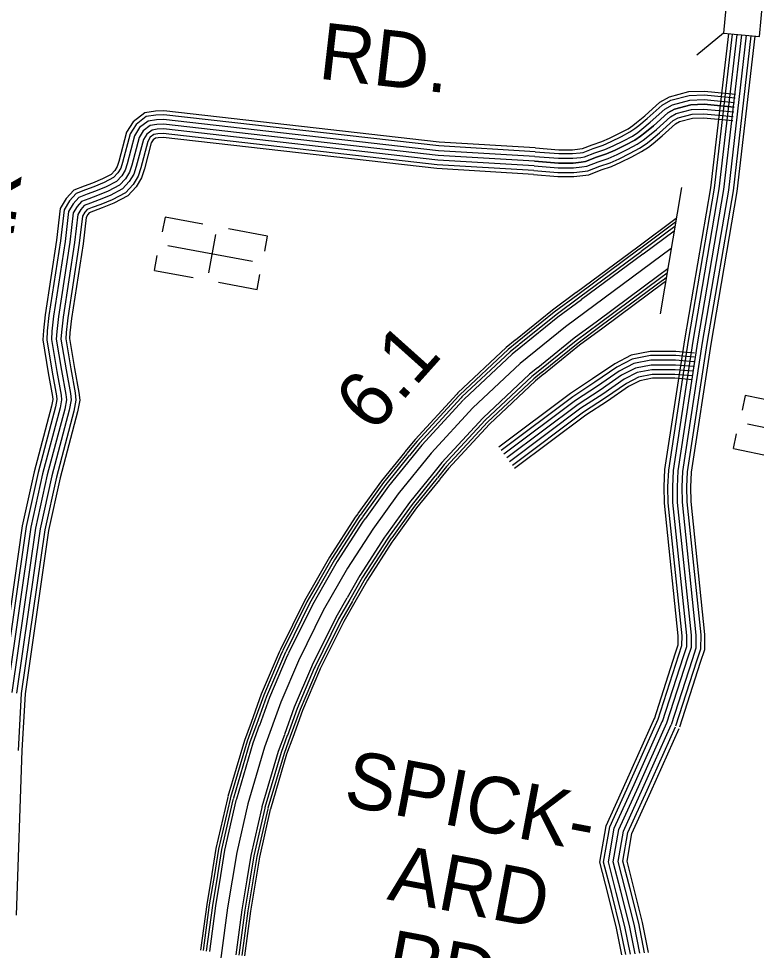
# Model space of a CAD drawing. Extents: x 1788175 to 1969470, y 584502 to 738744.
# Drawn here: x 1840962 to 1845792, y 638570 to 644675 of the extents above; entities that cross this region are included whole.
import ezdxf

# ---------------------------------------------------------------- set-up
doc = ezdxf.new("R2010")
doc.units = 0
for name, color, linetype in [('DESIGN - ROW - Right-of-Way and Easement Labels', 7, 'Continuous'), ('DESIGN - TRAFFIC CONTROL PERMANENT - Signalization', 7, 'Continuous'), ('DESIGN - UTILITIES - Cable (Underground) with Text', 7, 'Continuous'), ('SURVEY - CENTERLINE - Preliminary Text', 7, 'Continuous'), ('SURVEY - CONTOURS - Index with Text', 7, 'Continuous'), ('SURVEY - DRAINAGE - Storm Sewer', 7, 'Continuous'), ('SURVEY - TRANSPORTATION - Roads', 7, 'Continuous')]:
    doc.layers.add(name, color=color, linetype=linetype)

msp = doc.modelspace()

# ---------------------------------------------------------------- linework, layer by layer
at = {"layer": 'DESIGN - UTILITIES - Cable (Underground) with Text'}
for p, q in [((1841920, 643374.4), (1841902.2, 643277.8)), ((1842167.3, 643328.8), (1841920.1, 643374.5)), ((1842206.8, 643010.1), (1842252.8, 643259.5)), ((1842591.9, 643250.4), (1842335.4, 643297.8)), ((1842573.8, 643152.4), (1842591.8, 643249.8)), ((1841851.5, 643025.1), (1841869.6, 643122.9)), ((1841851.4, 643024.9), (1842105.3, 642978)), ((1842523.3, 642900.7), (1842541.4, 642998.8)), ((1842270.8, 642947.4), (1842523.3, 642900.8)), ((1845718.1, 642205.9), (1845698.2, 642109.8)), ((1845964.4, 642154.9), (1845718.2, 642206.1)), ((1845641.9, 641858.2), (1845662.1, 641955.6)), ((1845641.8, 641858), (1845894.5, 641805.5))]:
    msp.add_line(p, q, dxfattribs=at)
for points in [[(1842492.8, 643084.7), (1841939.1, 643187)], [(1846284.3, 641903.7), (1845733.1, 642018.2)]]:
    msp.add_lwpolyline(points, dxfattribs=at)
at = {"layer": 'SURVEY - CENTERLINE - Preliminary Text'}
for points in [[(1845268, 643365.2), (1845016.2, 643178.6)], [(1845263.8, 643340.3), (1845026.6, 643164.5)], [(1845259.1, 643311.9), (1845038.5, 643148.5)], [(1845254.3, 643283.1), (1845050.6, 643132.2)], [(1845235.2, 643168.5), (1844542.4, 642655.1), (1844245.9, 642415.6), (1843936.4, 642125.1), (1843661.9, 641827.2), (1843447.3, 641561.6), (1843279.8, 641329.3), (1843115.9, 641075.5), (1842956.4, 640796.1), (1842793.7, 640466.7), (1842679.4, 640197.2), (1842572.4, 639902.6), (1842462.7, 639531), (1842389.5, 639210.6), (1842329.8, 638849.8), (1841456.3, 632272.6)], [(1845015.4, 643178), (1844613.7, 642880.4)], [(1845025.8, 643164), (1844624.1, 642866.3)], [(1845037.8, 643147.9), (1844636, 642850.2)], [(1845049.8, 643131.6), (1844648.1, 642833.9)], [(1845213, 643035.5), (1845154.4, 642992)], [(1845208.2, 643006.6), (1845167.2, 642976.3)], [(1845153.7, 642991.5), (1844752, 642693.8)], [(1845166.5, 642975.7), (1844764.8, 642678)], [(1845178.4, 642959.6), (1844776.7, 642662)], [(1845188.8, 642945.6), (1844787.1, 642647.9)], [(1845203.5, 642978.2), (1845179.1, 642960.2)], [(1845199.4, 642953.4), (1845189.5, 642946.1)], [(1844613, 642879.8), (1844457.6, 642764.7), (1844214.6, 642568.3)], [(1844623.4, 642865.8), (1844468.3, 642750.8), (1844225.6, 642554.7)], [(1844635.3, 642849.7), (1844480.5, 642735), (1844238.2, 642539.2)], [(1844647.4, 642833.4), (1844492.9, 642719), (1844250.9, 642523.4)], [(1844751.2, 642693.2), (1844599.7, 642581), (1844360.5, 642387.7)], [(1844764, 642677.5), (1844612.1, 642564.9), (1844374, 642372.5)], [(1844775.9, 642661.4), (1844624.4, 642549.1), (1844386.6, 642357)], [(1844786.4, 642647.4), (1844635.1, 642535.3), (1844397.6, 642343.4)], [(1844213.9, 642567.8), (1844154.9, 642520.1), (1843837.9, 642222.6), (1843831.3, 642215.4)], [(1844224.9, 642554.2), (1844166.4, 642506.9), (1843850.4, 642210.3), (1843844.2, 642203.6)], [(1844237.4, 642538.6), (1844179.5, 642491.8), (1843864.6, 642196.2), (1843858.9, 642190)], [(1844250.2, 642522.8), (1844192.9, 642476.5), (1843879, 642181.9), (1843873.8, 642176.3)], [(1844359.8, 642387.2), (1844307.5, 642344.9), (1844003, 642059.1), (1844002.1, 642058.1)], [(1844373.3, 642371.9), (1844320.9, 642329.6), (1844017.4, 642044.8), (1844017.6, 642045)], [(1844385.8, 642356.4), (1844334, 642314.5), (1844031.7, 642030.7), (1844032.3, 642031.5)], [(1844396.8, 642342.8), (1844345.5, 642301.3), (1844044.1, 642018.4), (1844045.2, 642019.6)], [(1843830.7, 642214.8), (1843557, 641917.8), (1843490.9, 641836)], [(1843843.6, 642202.9), (1843570.2, 641906.4), (1843504.5, 641825)], [(1843858.3, 642189.4), (1843585.4, 641893.3), (1843520.1, 641812.4)], [(1843873.2, 642175.6), (1843600.8, 641880), (1843535.8, 641799.7)], [(1844001.4, 642057.4), (1843732.9, 641766), (1843671.5, 641690.1)], [(1844017, 642044.3), (1843748.2, 641752.7), (1843687.9, 641678)], [(1844031.7, 642030.8), (1843763.4, 641739.7), (1843703.4, 641665.5)], [(1844044.6, 642018.9), (1843776.6, 641728.2), (1843717, 641654.5)], [(1843490.3, 641835.3), (1843337.2, 641645.8), (1843182.8, 641431.7)], [(1843503.9, 641824.3), (1843351.1, 641635.1), (1843197, 641421.5)], [(1843519.5, 641811.7), (1843367, 641623), (1843213.3, 641409.8)], [(1843535.3, 641799), (1843383.1, 641610.7), (1843229.7, 641397.9)], [(1843671, 641689.4), (1843521.8, 641504.8), (1843371.2, 641295.9)], [(1843687.3, 641677.3), (1843538, 641492.5), (1843388.2, 641284.7)], [(1843702.9, 641664.8), (1843553.9, 641480.3), (1843404.4, 641273)], [(1843716.5, 641653.8), (1843567.8, 641469.7), (1843418.6, 641262.8)], [(1843182.3, 641431), (1843165.4, 641407.5), (1842997.5, 641147.5), (1842910.1, 640994.4)], [(1843196.5, 641420.7), (1843179.8, 641397.6), (1843012.5, 641138.4), (1842925.3, 640985.8)], [(1843212.7, 641409), (1843196.4, 641386.3), (1843029.6, 641128), (1842942.7, 640975.8)], [(1843229.2, 641397.2), (1843213.1, 641374.9), (1843046.9, 641117.5), (1842960.3, 640965.8)], [(1843370.7, 641295.1), (1843357.2, 641276.5), (1843196, 641026.9), (1843111.7, 640879.3)], [(1843387.7, 641284), (1843374, 641265), (1843213.4, 641016.3), (1843129.8, 640870)], [(1843403.9, 641272.3), (1843390.5, 641253.8), (1843230.5, 641005.9), (1843147.2, 640860.1)], [(1843418.1, 641262.1), (1843405, 641243.9), (1843245.4, 640996.8), (1843162.4, 640851.4)], [(1842909.6, 640993.7), (1842834, 640861.2), (1842676.4, 640542.2)], [(1842924.8, 640985), (1842849.5, 640853), (1842692.1, 640534.4)], [(1842942.2, 640975.1), (1842867.1, 640843.6), (1842710.1, 640525.6)], [(1842959.8, 640965), (1842885, 640834), (1842728.2, 640516.6)], [(1843111.3, 640878.5), (1843039.1, 640752.1), (1842884.6, 640439.4)], [(1843129.4, 640869.2), (1843057, 640742.6), (1842903.2, 640431.2)], [(1843146.7, 640859.3), (1843074.7, 640733.2), (1842921.2, 640422.3)], [(1843161.9, 640850.6), (1843090.1, 640725), (1842936.9, 640414.6)], [(1842676, 640541.4), (1842667.7, 640524.5), (1842550.4, 640247.9), (1842483.5, 640063.6)], [(1842691.7, 640533.6), (1842683.6, 640517.2), (1842566.7, 640241.5), (1842499.9, 640057.6)], [(1842709.7, 640524.8), (1842701.8, 640508.8), (1842585.3, 640234.2), (1842518.7, 640050.8)], [(1842727.8, 640515.8), (1842720.2, 640500.4), (1842604.2, 640226.7), (1842537.8, 640043.9)], [(1842884.2, 640438.5), (1842878.9, 640427.6), (1842766.6, 640162.9), (1842701.8, 639984.4)], [(1842902.8, 640430.4), (1842897.3, 640419.2), (1842785.5, 640155.5), (1842721.1, 639978.3)], [(1842920.8, 640421.5), (1842915.5, 640410.9), (1842804.1, 640148.1), (1842739.9, 639971.5)], [(1842936.5, 640413.8), (1842931.4, 640403.6), (1842820.4, 640141.7), (1842756.4, 639965.5)], [(1842483.2, 640062.8), (1842440.8, 639945.9), (1842332, 639577.5)], [(1842499.6, 640056.8), (1842457.4, 639940.5), (1842348.8, 639572.5)], [(1842518.4, 640050), (1842476.4, 639934.2), (1842367.9, 639566.9)], [(1842537.5, 640043.1), (1842495.7, 639927.9), (1842387.4, 639561.1)], [(1842701.5, 639983.5), (1842661.5, 639873.4), (1842554.7, 639511.7)], [(1842720.8, 639977.5), (1842680.7, 639867), (1842574.4, 639506.9)], [(1842739.6, 639970.6), (1842699.7, 639860.8), (1842593.6, 639501.2)], [(1842756.1, 639964.7), (1842716.4, 639855.3), (1842610.4, 639496.2)], [(1842331.7, 639576.6), (1842328.6, 639566.1), (1842253.5, 639237.3), (1842226, 639070.7)], [(1842348.5, 639571.7), (1842345.6, 639561.7), (1842270.7, 639233.9), (1842243.2, 639067.9)], [(1842367.7, 639566), (1842364.9, 639556.6), (1842290.3, 639230.1), (1842263, 639064.6)], [(1842387.1, 639560.2), (1842384.6, 639551.5), (1842310.2, 639226.2), (1842283, 639061.3)], [(1842554.4, 639510.8), (1842553.4, 639507.3), (1842481.5, 639192.5), (1842455.1, 639032.8)], [(1842574.1, 639506), (1842573, 639502.2), (1842501.4, 639188.6), (1842475.2, 639030.4)], [(1842593.3, 639500.3), (1842592.4, 639497.1), (1842521, 639184.7), (1842495, 639027.1)], [(1842610.1, 639495.4), (1842609.3, 639492.7), (1842538.2, 639181.3), (1842512.2, 639024.3)], [(1842225.8, 639069.8), (1842192.8, 638870.2), (1842153, 638570.8)], [(1842243.1, 639067), (1842210.1, 638867.6), (1842170.4, 638568.4)], [(1842262.8, 639063.7), (1842229.9, 638864.7), (1842190.2, 638565.8)], [(1842282.8, 639060.4), (1842249.9, 638861.7), (1842210.3, 638563.1)], [(1842454.9, 639031.9), (1842422.5, 638835.9), (1842383.2, 638540.2)], [(1842475.1, 639029.5), (1842442.6, 638832.9), (1842403.4, 638538.4)], [(1842494.8, 639026.2), (1842462.3, 638830), (1842423.3, 638535.8)], [(1842512.1, 639023.4), (1842479.7, 638827.4), (1842440.6, 638533.5)]]:
    msp.add_lwpolyline(points, dxfattribs=at)
at = {"layer": 'SURVEY - CONTOURS - Index with Text'}
for points in [[(1845124.4, 640087.2), (1845261.4, 640513.5), (1845280.4, 640571.4), (1845281.1, 640631), (1845190.3, 641500.3), (1845188.9, 641608.7), (1845193.9, 641719.9), (1845323.7, 642570.7), (1845494.4, 643567.1), (1845611, 644576.4)], [(1845147.9, 640079.6), (1845284.9, 640505.9), (1845305, 640567.3), (1845305.9, 640632.1), (1845215, 641501.8), (1845213.6, 641608.3), (1845218.5, 641717.4), (1845348.1, 642566.7), (1845518.9, 643563.6), (1845635.6, 644574.1)], [(1845177.4, 640070.1), (1845314.4, 640496.3), (1845336, 640562.1), (1845336.9, 640633.6), (1845246, 641503.6), (1845244.6, 641607.8), (1845249.4, 641714.4), (1845378.7, 642561.8), (1845549.6, 643559.2), (1845666.5, 644571.2)], [(1845206.9, 640060.6), (1845343.8, 640486.7), (1845366.9, 640557), (1845367.9, 640635), (1845276.9, 641505.4), (1845275.6, 641607.3), (1845280.3, 641711.4), (1845409.3, 642556.8), (1845580.3, 643554.8), (1845697.3, 644568.4)], [(1845206.9, 640060.6), (1845343.8, 640486.7), (1845366.9, 640557), (1845367.9, 640635), (1845276.9, 641505.4), (1845275.6, 641607.3), (1845280.3, 641711.4), (1845409.3, 642556.8), (1845580.3, 643554.8), (1845697.3, 644568.3)], [(1845236.4, 640051.1), (1845373.3, 640477.1), (1845397.8, 640551.8), (1845398.9, 640636.4), (1845307.9, 641507.2), (1845306.6, 641606.8), (1845311.2, 641708.3), (1845439.9, 642551.9), (1845611, 643550.4), (1845728.2, 644565.5)], [(1845265.9, 640041.7), (1845402.8, 640467.6), (1845428.8, 640546.7), (1845430, 640637.8), (1845338.9, 641509), (1845337.7, 641606.3), (1845342.1, 641705.3), (1845470.5, 642546.9), (1845641.7, 643546), (1845759.1, 644562.6)], [(1845290.4, 640033.8), (1845427.3, 640459.6), (1845454.4, 640542.4), (1845455.7, 640639), (1845364.6, 641510.5), (1845363.4, 641605.9), (1845367.7, 641702.8), (1845495.9, 642542.8), (1845667.2, 643542.4), (1845784.7, 644560.2)], [(1845646.8, 644094.8), (1845449.7, 644113.6), (1845362.1, 644110.5), (1845255.7, 644082.3), (1845211.9, 644057.3), (1845118, 643972.8), (1845061.7, 643925.9), (1845033.6, 643904), (1844996, 643879), (1844936.6, 643847.7), (1844867.8, 643813.3), (1844811.4, 643788.2), (1844745.7, 643766.3), (1844673.8, 643738.2), (1844645.6, 643735), (1844592.5, 643728.8), (1844495.5, 643728.8), (1844339, 643741)], [(1844344.3, 643828.5), (1843715.8, 643866.1), (1841912.7, 644071.5), (1841857.2, 644068.2), (1841787.3, 644057.7), (1841711, 643999.6), (1841668.2, 643930.3), (1841617.9, 643739.8), (1841606.5, 643705.4), (1841590.7, 643679.1), (1841567.6, 643654.2), (1841511.3, 643624.2), (1841445.1, 643597.4), (1841389.9, 643576.8), (1841322.5, 643550.5), (1841273.3, 643496.5), (1841233.6, 643430.3), (1841210.1, 643222.9), (1841134.4, 642733.9), (1841123.3, 642632), (1841119.1, 642569.9), (1841155.5, 642353.8), (1841183.1, 642200.1), (1841185.6, 642180.1), (1841177.5, 642136.5), (1841063.5, 641706.5), (1840985, 641352.6), (1840830, 640267.8)], [(1844342.7, 643802.9), (1843713.6, 643840.5), (1841912, 644045.7), (1841859.9, 644042.6), (1841797.6, 644033.3), (1841730.3, 643982.1), (1841692.1, 643920.1), (1841642.6, 643732.4), (1841630, 643694.6), (1841611.4, 643663.6), (1841583.5, 643633.5), (1841522.2, 643600.9), (1841454.4, 643573.5), (1841399.1, 643552.8), (1841337.5, 643528.7), (1841294, 643481.1), (1841258.5, 643421.9), (1841235.6, 643219.5), (1841159.9, 642730.5), (1841148.9, 642629.7), (1841145, 642571.2), (1841180.8, 642358.2), (1841208.5, 642204), (1841211.6, 642179.3), (1841202.6, 642130.9), (1841088.5, 641700.5), (1841010.3, 641348), (1840855.6, 640265.3)], [(1844340.9, 643771.9), (1843710.9, 643809.6), (1841911.1, 644014.6), (1841863.2, 644011.8), (1841810.1, 644003.8), (1841753.7, 643960.9), (1841720.9, 643907.7), (1841672.3, 643723.6), (1841658.3, 643681.6), (1841636.3, 643644.9), (1841602.6, 643608.6), (1841535.3, 643572.8), (1841465.7, 643544.6), (1841410.2, 643523.9), (1841355.5, 643502.5), (1841319, 643462.4), (1841288.6, 643411.7), (1841266.3, 643215.4), (1841190.7, 642726.5), (1841179.8, 642627), (1841176.2, 642572.7), (1841211.4, 642363.5), (1841239.2, 642208.6), (1841242.9, 642178.3), (1841232.8, 642124.1), (1841118.6, 641693.1), (1841040.8, 641342.4), (1840886.5, 640262.2)], [(1844339, 643741), (1843708.2, 643778.7), (1841910.3, 643983.5), (1841866.4, 643980.9), (1841822.5, 643974.3), (1841777, 643939.7), (1841749.7, 643895.3), (1841702, 643714.7), (1841686.6, 643668.5), (1841661.2, 643626.2), (1841621.8, 643583.7), (1841548.4, 643544.7), (1841476.9, 643515.7), (1841421.3, 643494.9), (1841373.6, 643476.2), (1841344, 643443.8), (1841318.6, 643401.5), (1841297.1, 643211.3), (1841221.4, 642722.4), (1841210.7, 642624.3), (1841207.3, 642574.3), (1841241.9, 642368.8), (1841269.9, 642213.3), (1841274.3, 642177.4), (1841263.1, 642117.2), (1841148.8, 641685.8), (1841071.3, 641336.9), (1840917.3, 640259.1)], [(1844339, 643741), (1843708.2, 643778.7), (1841910.3, 643983.5), (1841866.4, 643980.9), (1841822.5, 643974.3), (1841777, 643939.7), (1841749.7, 643895.3), (1841702, 643714.7), (1841686.6, 643668.5), (1841661.2, 643626.2), (1841621.8, 643583.7), (1841548.4, 643544.7), (1841476.9, 643515.7), (1841421.3, 643494.9), (1841373.6, 643476.2), (1841344, 643443.8), (1841318.6, 643401.5), (1841297.1, 643211.3), (1841221.4, 642722.4), (1841210.7, 642624.3), (1841207.3, 642574.3), (1841241.9, 642368.8), (1841269.9, 642213.3), (1841274.3, 642177.4), (1841263.1, 642117.2), (1841148.8, 641685.8), (1841071.3, 641336.9), (1840917.3, 640259.1)], [(1844337.2, 643710), (1843705.5, 643747.8), (1841909.4, 643952.4), (1841869.6, 643950.1), (1841835, 643944.8), (1841800.4, 643918.5), (1841778.5, 643883), (1841731.8, 643705.9), (1841715, 643655.5), (1841686.1, 643607.5), (1841641, 643558.7), (1841561.6, 643516.5), (1841488.1, 643486.8), (1841432.3, 643465.9), (1841391.6, 643450), (1841369, 643425.2), (1841348.6, 643391.3), (1841327.8, 643207.2), (1841252.2, 642718.4), (1841241.6, 642621.6), (1841238.5, 642575.8), (1841272.4, 642374.2), (1841300.5, 642217.9), (1841305.7, 642176.4), (1841293.3, 642110.4), (1841178.9, 641678.5), (1841101.9, 641331.3), (1840948.2, 640256)], [(1844335.3, 643679.1), (1843702.9, 643716.9), (1841908.6, 643921.3), (1841872.9, 643919.2), (1841847.5, 643915.4), (1841823.8, 643897.3), (1841807.3, 643870.6), (1841761.5, 643697), (1841743.3, 643642.5), (1841711.1, 643588.8), (1841660.2, 643533.8), (1841574.7, 643488.4), (1841499.4, 643457.9), (1841443.4, 643437), (1841409.6, 643423.8), (1841394, 643406.6), (1841378.7, 643381.1), (1841358.5, 643203), (1841282.9, 642714.3), (1841272.5, 642618.9), (1841269.7, 642577.4), (1841303, 642379.5), (1841331.2, 642222.6), (1841337, 642175.4), (1841323.6, 642103.6), (1841209, 641671.1), (1841132.4, 641325.7), (1840979.1, 640253), (1840958.1, 639880.1)], [(1844333.9, 643654.4), (1843700.7, 643692.2), (1841907.9, 643896.5), (1841875.4, 643894.6), (1841857.4, 643891.9), (1841842.4, 643880.4), (1841830.2, 643860.7), (1841785.2, 643689.9), (1841765.9, 643632.1), (1841730.9, 643573.9), (1841675.5, 643514), (1841585.2, 643466), (1841508.4, 643434.8), (1841452.2, 643413.9), (1841424, 643402.9), (1841413.9, 643391.8), (1841402.7, 643373), (1841383, 643199.8), (1841307.4, 642711.1), (1841297.1, 642616.7), (1841294.5, 642578.6), (1841327.3, 642383.7), (1841355.6, 642226.3), (1841362, 642174.7), (1841347.7, 642098.1), (1841233, 641665.3), (1841156.7, 641321.3), (1841003.7, 640250.5), (1840982.8, 639879), (1840944.6, 638801.2)], [(1844912, 638540.1), (1844876.6, 638715.1), (1844821.2, 638936.3), (1844767, 639147.5), (1844808.1, 639387.2), (1844941.9, 639680.5), (1845127.8, 640096)], [(1844936.8, 638542.6), (1844900.7, 638720.5), (1844845.2, 638942.4), (1844792.2, 639148.6), (1844831.9, 639379.9), (1844964.4, 639670.3), (1845150.3, 640085.9)], [(1844967.8, 638545.6), (1844931, 638727.4), (1844875.2, 638950), (1844823.9, 639149.9), (1844861.8, 639370.7), (1844992.7, 639657.5), (1845178.6, 640073.3)], [(1844998.8, 638548.6), (1844961.2, 638734.2), (1844905.3, 638957.6), (1844855.6, 639151.1), (1844891.6, 639361.5), (1845020.9, 639644.8), (1845206.9, 640060.6)], [(1845029.8, 638551.6), (1844991.4, 638741.1), (1844935.3, 638965.3), (1844887.3, 639152.4), (1844921.5, 639352.3), (1845049.2, 639632), (1845235.2, 640048)], [(1845060.8, 638554.6), (1845021.7, 638747.9), (1844965.4, 638972.9), (1844918.9, 639153.7), (1844951.4, 639343.1), (1845077.4, 639619.3), (1845263.5, 640035.3)], [(1845086.6, 638557.1), (1845046.8, 638753.6), (1844990.3, 638979.2), (1844945.2, 639154.8), (1844976.2, 639335.4), (1845100.9, 639608.7), (1845287, 640024.8)]]:
    msp.add_lwpolyline(points, dxfattribs=at)
at = {"layer": 'SURVEY - DRAINAGE - Storm Sewer'}
msp.add_line((1845576.5, 644579.6), (1845401.8, 644434.6), dxfattribs=at)
msp.add_lwpolyline([(1845598.6, 644816.2), (1845576.5, 644579.6), (1845813.1, 644557.6), (1845835.1, 644794.2)], close=True, dxfattribs=at)
msp.add_lwpolyline([(1845301, 643569.2), (1845162.8, 642739.8)], dxfattribs=at)
at = {"layer": 'SURVEY - TRANSPORTATION - Roads'}
for points in [[(1844343.9, 643802.8), (1844497.9, 643790.8), (1844588.8, 643790.8), (1844638.6, 643796.6), (1844658.8, 643798.9), (1844724.6, 643824.6), (1844789, 643846.1), (1844841.3, 643869.3), (1844908.3, 643902.8), (1844964.3, 643932.3), (1844997.3, 643954.3), (1845022.8, 643974.2), (1845077.4, 644019.7), (1845175.4, 644107.8), (1845232, 644140.2), (1845352.9, 644172.2), (1845451.5, 644175.7), (1845652.6, 644156.5)], [(1844345.8, 643827.4), (1844498.9, 643815.5), (1844587.4, 643815.5), (1844635.8, 643821.2), (1844652.9, 643823.1), (1844716.2, 643847.9), (1844780, 643869.2), (1844830.7, 643891.7), (1844897, 643924.8), (1844951.7, 643953.6), (1844982.8, 643974.4), (1845007.3, 643993.4), (1845061.3, 644038.4), (1845160.8, 644128), (1845222.5, 644163.2), (1845349.3, 644196.8), (1845452.2, 644200.5), (1845655, 644181.1)], [(1844339, 643741), (1844495.5, 643728.8), (1844592.5, 643728.8), (1844645.6, 643735), (1844673.8, 643738.2), (1844745.7, 643766.3), (1844811.4, 643788.2), (1844867.8, 643813.3), (1844936.6, 643847.7), (1844996, 643879), (1845033.6, 643904), (1845061.7, 643925.9), (1845118, 643972.8), (1845211.9, 644057.3), (1845255.7, 644082.3), (1845362.1, 644110.5), (1845449.7, 644113.6), (1845646.8, 644094.8)], [(1844341.4, 643771.9), (1844496.7, 643759.8), (1844590.6, 643759.8), (1844642.1, 643765.8), (1844666.3, 643768.5), (1844735.2, 643795.5), (1844800.2, 643817.2), (1844854.5, 643841.3), (1844922.4, 643875.3), (1844980.2, 643905.6), (1845015.4, 643929.2), (1845042.3, 643950), (1845097.7, 643996.2), (1845193.6, 644082.5), (1845243.8, 644111.2), (1845357.5, 644141.3), (1845450.6, 644144.6), (1845649.7, 644125.7)], [(1844334.2, 643679.2), (1844493.1, 643666.8), (1844596.1, 643666.8), (1844652.7, 643673.4), (1844688.8, 643677.5), (1844766.9, 643708), (1844833.9, 643730.4), (1844894.2, 643757.2), (1844964.9, 643792.5), (1845027.8, 643825.6), (1845069.8, 643853.7), (1845100.6, 643877.6), (1845158.6, 643925.9), (1845248.4, 644006.7), (1845279.4, 644024.5), (1845371.2, 644048.8), (1845447.8, 644051.5), (1845640.9, 644033.1)], [(1844336.6, 643710.1), (1844494.3, 643697.8), (1844594.3, 643697.8), (1844649.2, 643704.2), (1844681.3, 643707.8), (1844756.3, 643737.2), (1844822.7, 643759.3), (1844881, 643785.2), (1844950.7, 643820.1), (1845011.9, 643852.3), (1845051.7, 643878.8), (1845081.2, 643901.7), (1845138.3, 643949.4), (1845230.2, 644032), (1845267.6, 644053.4), (1845366.6, 644079.6), (1845448.7, 644082.5), (1845643.8, 644064)], [(1844332.2, 643653.5), (1844492.1, 643641.1), (1844597.6, 643641.1), (1844655.6, 643647.9), (1844695, 643652.3), (1844775.6, 643683.8), (1844843.2, 643706.4), (1844905.2, 643733.9), (1844976.6, 643769.6), (1845040.9, 643803.5), (1845084.9, 643832.8), (1845116.7, 643857.6), (1845175.5, 643906.5), (1845263.6, 643985.8), (1845289.2, 644000.5), (1845375, 644023.2), (1845447.1, 644025.7), (1845638.4, 644007.5)], [(1845386.8, 642482.8), (1845265.7, 642493.1), (1845096, 642493.1), (1844971.4, 642469), (1844864.7, 642413.6), (1844720.3, 642313.9), (1844574.8, 642219), (1844104.9, 641866.7)], [(1845384.6, 642457.1), (1845264.6, 642467.4), (1845098.5, 642467.4), (1844979.9, 642444.5), (1844878, 642391.6), (1844734.7, 642292.5), (1844589.5, 642198), (1844120.3, 641846.2)], [(1845382, 642426.3), (1845263.3, 642436.4), (1845101.5, 642436.4), (1844990.2, 642414.9), (1844894, 642365), (1844752, 642266.8), (1844607.3, 642172.5), (1844138.9, 641821.4)], [(1845379.3, 642395.4), (1845262, 642405.4), (1845104.4, 642405.4), (1845000.5, 642385.3), (1844910, 642338.3), (1844769.2, 642241), (1844625.1, 642147.1), (1844157.5, 641796.6)], [(1845379.3, 642395.4), (1845262, 642405.4), (1845104.4, 642405.4), (1845000.5, 642385.3), (1844910, 642338.3), (1844769.2, 642241.1), (1844625.1, 642147.1), (1844157.5, 641796.6)], [(1845376.7, 642364.5), (1845260.7, 642374.4), (1845107.4, 642374.4), (1845010.8, 642355.7), (1844926, 642311.7), (1844786.5, 642215.3), (1844642.9, 642121.7), (1844176.1, 641771.8)], [(1845374, 642333.6), (1845259.3, 642343.4), (1845110.4, 642343.4), (1845021.1, 642326.1), (1844942, 642285.1), (1844803.8, 642189.6), (1844660.7, 642096.3), (1844194.7, 641747)], [(1845371.9, 642309), (1845258.3, 642318.7), (1845112.7, 642318.7), (1845029.3, 642302.6), (1844954.8, 642263.9), (1844817.6, 642169), (1844674.8, 642076), (1844209.5, 641727.2)]]:
    msp.add_lwpolyline(points, dxfattribs=at)

# ---------------------------------------------------------------- texts
at = {"layer": 'DESIGN - ROW - Right-of-Way and Easement Labels'}
for s, rotation, p in [('RD.', 353.49961, (1842917.5, 644282.7)), ('OAK', 81.86793, (1840834.2, 642612.1)), ('SPICK-', 349.30671, (1843079.6, 639523)), ('ARD', 349.30671, (1843368.3, 638905.3)), ('RD.', 349.30671, (1843348.9, 638344.2))]:
    msp.add_text(s, height=370, rotation=rotation, dxfattribs=at).set_placement(p)
at = {"layer": 'DESIGN - TRAFFIC CONTROL PERMANENT - Signalization'}
msp.add_text('6.1', height=370, rotation=48.12605, dxfattribs=at).set_placement((1843280.7, 641950.9))

doc.saveas('drawing.dxf')
